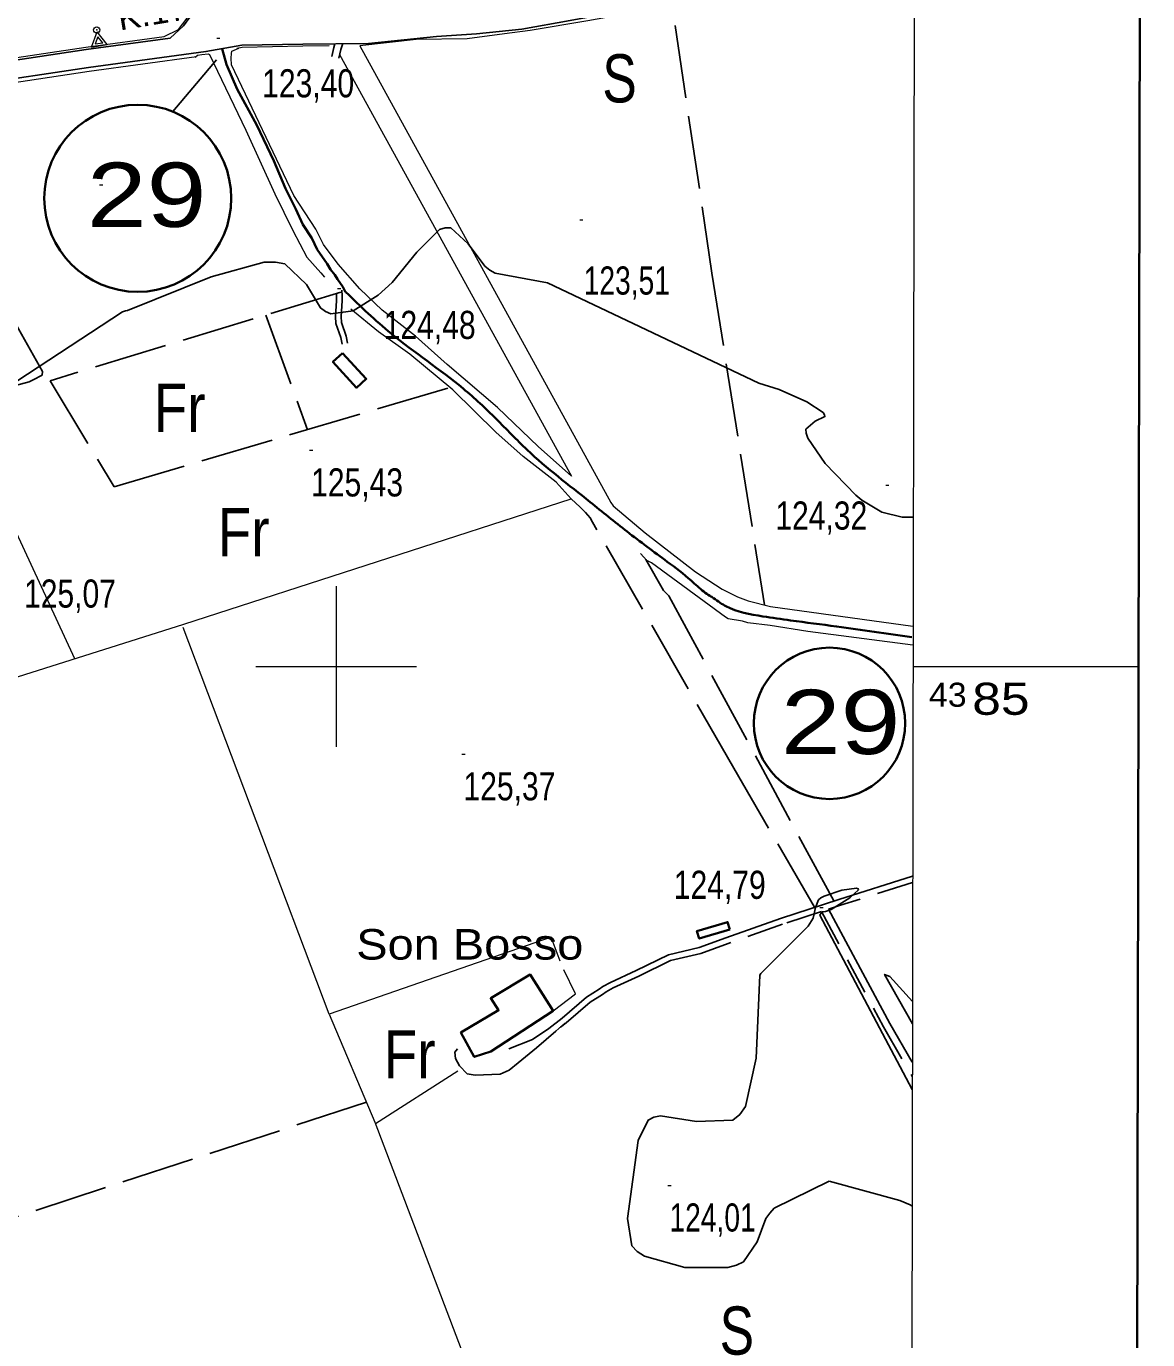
# Model space of a CAD drawing. Extents: x 483847 to 488453, y 4383581 to 4386795.
# Drawn here: x 487403.6 to 487752.5, y 4384790.5 to 4385199.2 of the extents above; entities that cross this region are included whole.
import ezdxf
from ezdxf.enums import TextEntityAlignment as Align

# ---------------------------------------------------------------- set-up
doc = ezdxf.new("R2010")
doc.units = 0
doc.header["$LTSCALE"] = 3.8
doc.header["$PDMODE"] = 32
doc.header["$PDSIZE"] = 1.9
for name, pattern in [('DOTTED', [1.5, 0.3, -1.2]), ('LONG_DASHED', [7.5, 6, -1.5]), ('MEDIUM_DASHED', [4.5, 3, -1.5])]:
    doc.linetypes.add(name, pattern=pattern)
for name, color, linetype, lineweight in [('1', 7, 'Continuous', 13), ('13', 7, 'Continuous', 25), ('2', 7, 'DOTTED', 13), ('25', 7, 'LONG_DASHED', 25), ('36', 7, 'Continuous', 25), ('38', 7, 'Continuous', 25), ('41', 7, 'Continuous', 13), ('47', 7, 'Continuous', 35), ('51', 7, 'Continuous', 13), ('6', 7, 'Continuous', 35), ('7', 7, 'Continuous', 13), ('8', 7, 'Continuous', 25)]:
    doc.layers.add(name, color=color, linetype=linetype, lineweight=lineweight)
doc.layers.add('31', color=7, linetype='Continuous')
doc.layers.add('5', color=7, linetype='Continuous')

msp = doc.modelspace()

# ---------------------------------------------------------------- linework, layer by layer
at = {"layer": '1'}
for p, q in [((487500, 4385025), (487500, 4384975)), ((487475, 4385000), (487525, 4385000)), ((487679.47, 4385000), (487749.65, 4385000))]:
    msp.add_line(p, q, dxfattribs=at)
at = {"layer": '1', "lineweight": 35}
msp.add_lwpolyline([(484035.03, 4386519.58), (487752.53, 4386512.52), (487747.86, 4384057.52), (484030.36, 4384064.59)], close=True, dxfattribs=at)
at = {"layer": '1'}
msp.add_lwpolyline([(484105.5, 4386448.1), (487681.9, 4386441.2), (487678, 4384129), (484100.5, 4384135.8)], close=True, dxfattribs=at)
at = {"layer": '25'}
for p, q in [((487478.05, 4385109.37), (487491.04, 4385073.7)), ((487509.45, 4384864.45), (487305.11, 4384797.64))]:
    msp.add_line(p, q, dxfattribs=at)
for points in [[(487605.49, 4385199.49), (487616.92, 4385122.4), (487633.25, 4385019.22)], [(487348.87, 4385070.84), (487382.28, 4385079.84), (487383.6, 4385083.12), (487404.46, 4385088.6), (487405.67, 4385089.19), (487408.47, 4385090.65), (487408.64, 4385091.85), (487380.97, 4385140.87), (487317.71, 4385128.68)], [(487501.43, 4385116.48), (487411, 4385088.96), (487430.86, 4385055.89), (487535.45, 4385086.85)], [(487648.8, 4384925.1), (487623.72, 4384968.41), (487579.8, 4385044.9), (487578.99, 4385046.26), (487577.59, 4385047.93), (487576.85, 4385048.69), (487575.89, 4385049.61), (487573.15, 4385052.2)], [(487654.85, 4384927.07), (487609.04, 4385011.84), (487603.48, 4385021.97), (487601.85, 4385023.72), (487596.36, 4385033.36)]]:
    msp.add_lwpolyline(points, dxfattribs=at)
at = {"layer": '36'}
for points in [[(486825.52, 4385103.44), (486853.12, 4385107.17), (486880.63, 4385110.38), (486915.74, 4385115.13), (486950.76, 4385119.43), (487008.87, 4385126.93), (487067.66, 4385134.49), (487152.91, 4385145.5), (487220.82, 4385155.63), (487295.65, 4385167.08), (487350.85, 4385175.59), (487422.95, 4385186.43), (487459.43, 4385191.37), (487470.68, 4385193.32), (487489.65, 4385193.71), (487510.01, 4385193.94), (487531.2, 4385196.06), (487543.67, 4385196.93), (487557.74, 4385198.3), (487572.8, 4385201.01), (487598.91, 4385205.81), (487622.06, 4385209.39), (487655.21, 4385214.16), (487679.8, 4385218.38)], [(487455.81, 4385215.58), (487456.62, 4385209.72), (487455.81, 4385205.68), (487454.49, 4385202.09), (487452.5, 4385199.34), (487448.32, 4385195.53)], [(486788.13, 4385103.8), (486799.99, 4385105.59), (486824.76, 4385108.99), (486852.42, 4385112.73), (486879.93, 4385115.94), (486915.02, 4385120.69), (486950.06, 4385124.99), (487008.15, 4385132.49), (487066.94, 4385140.05), (487152.14, 4385151.05), (487219.98, 4385161.17), (487294.79, 4385172.63), (487350, 4385181.14), (487422.16, 4385191.98), (487448.32, 4385195.53)]]:
    msp.add_lwpolyline(points, dxfattribs=at)
at = {"layer": '38'}
for p, q in [((487679.36, 4384934.79), (487679.34, 4384934.78)), ((487679.25, 4384876.89), (487679.26, 4384876.87))]:
    msp.add_line(p, q, dxfattribs=at)
at = {"layer": '38', "linetype": 'MEDIUM_DASHED'}
for p, q in [((487679.36, 4384932.79), (487679.34, 4384932.79)), ((487679.24, 4384872.41), (487679.25, 4384872.39))]:
    msp.add_line(p, q, dxfattribs=at)
at = {"layer": '38'}
for points in [[(487499.62, 4385193.82), (487499.24, 4385192.62), (487498.6, 4385189.82)], [(487501.78, 4385117.18), (487501.83, 4385115.43), (487501.81, 4385113.77), (487501.59, 4385108.9), (487501.63, 4385107.1), (487503.13, 4385102.84), (487503.56, 4385100.63)], [(487679.34, 4384934.78), (487656.36, 4384927.55), (487638.26, 4384921.66), (487621.28, 4384915.6), (487612.93, 4384912.58), (487603.42, 4384910.3), (487593.39, 4384905.4), (487585.38, 4384901.75), (487582.98, 4384900.41), (487581.84, 4384899.59), (487577.88, 4384897.09), (487570.34, 4384890.65), (487566.12, 4384887.35), (487561.03, 4384884.01), (487553.76, 4384881.06)], [(487653.2, 4384924.53), (487672.28, 4384888.95), (487679.25, 4384876.89)], [(487537.76, 4384881.02), (487536.91, 4384879.98), (487537.11, 4384878.03), (487538.36, 4384875.76), (487540.8, 4384873.32), (487543.27, 4384872.84), (487551, 4384873.18), (487553.87, 4384874.41), (487556.6, 4384876.7), (487562.3, 4384881.42), (487568.37, 4384886.51), (487571.11, 4384889.02)]]:
    msp.add_lwpolyline(points, dxfattribs=at)
at = {"layer": '38', "linetype": 'MEDIUM_DASHED'}
for points in [[(487502.02, 4385193.85), (487501.45, 4385192.02), (487500.83, 4385189.31)], [(487500.04, 4385116.24), (487500.06, 4385115.42), (487500.04, 4385113.82), (487499.82, 4385108.92), (487499.86, 4385106.78), (487501.42, 4385102.37), (487501.82, 4385100.29)], [(487679.34, 4384932.79), (487656.93, 4384925.75), (487653.2, 4384924.53)], [(487651.03, 4384923.83), (487638.87, 4384919.86), (487621.92, 4384913.81), (487613.48, 4384910.76), (487604.06, 4384908.5), (487594.2, 4384903.68), (487586.23, 4384900.06), (487584, 4384898.8), (487582.9, 4384898.01), (487579.01, 4384895.55), (487571.54, 4384889.18), (487569.75, 4384887.78)], [(487651.03, 4384923.83), (487670.32, 4384887.86), (487679.24, 4384872.41)]]:
    msp.add_lwpolyline(points, dxfattribs=at)
at = {"layer": '41'}
for p, q in [((487423.82, 4385192.79), (487425.57, 4385197.47)), ((487428.75, 4385193.61), (487425.57, 4385197.47)), ((487423.82, 4385192.79), (487428.75, 4385193.61))]:
    msp.add_line(p, q, dxfattribs=at)
msp.add_lwpolyline([(487425.82, 4385195.99), (487424.98, 4385193.74), (487427.34, 4385194.14)], close=True, dxfattribs=at)
msp.add_point((487425.46, 4385198.13), dxfattribs=at)
at = {"layer": '47'}
for points in [[(487501.99, 4385097.56), (487509.35, 4385089.54), (487506.34, 4385086.77), (487498.98, 4385094.79)], [(487622.48, 4384918.15), (487612.96, 4384915.35), (487612.27, 4384917.7), (487621.79, 4384920.5)], [(487567.49, 4384892.9), (487548.1, 4384880.2), (487542.97, 4384878.54), (487538.8, 4384886.11), (487550.53, 4384893.07), (487548.11, 4384896.78), (487560.37, 4384904.18)]]:
    msp.add_lwpolyline(points, close=True, dxfattribs=at)
at = {"layer": '51'}
for p, q in [((487382.94, 4385079.31), (487418.61, 4385002.51)), ((487679.47, 4385012.54), (487679.49, 4385012.54)), ((487679.48, 4385006.7), (487679.46, 4385006.7)), ((487512.24, 4384857.84), (487537.81, 4384874.19))]:
    msp.add_line(p, q, dxfattribs=at)
for points in [[(487446.47, 4385196.1), (487450.9, 4385198.24), (487453.66, 4385201.8), (487454.46, 4385205.17), (487454.82, 4385209.52), (487454.85, 4385211.69), (487454.89, 4385214.69), (487452.92, 4385218.7), (487436.12, 4385261.03), (487431.32, 4385261.25), (487430.48, 4385265.47), (487383.24, 4385257.36)], [(487602.05, 4385205.23), (487578.28, 4385200.99), (487560.38, 4385197.95), (487552.34, 4385196.94), (487540.76, 4385195.3), (487524.85, 4385195.16), (487507.33, 4385193.16)], [(486912.94, 4385121.23), (486914.92, 4385121.49), (486949.96, 4385125.79), (487008.05, 4385133.29), (487066.84, 4385140.85), (487152.03, 4385151.85), (487219.86, 4385161.97), (487294.67, 4385173.43), (487349.88, 4385181.94), (487422.04, 4385192.78), (487446.47, 4385196.1)], [(487500.99, 4385190.47), (487573.17, 4385059.25), (487562.8, 4385068.48), (487550.22, 4385080.66), (487534.5, 4385094.02), (487524.65, 4385102.86), (487514.26, 4385110.89), (487507.38, 4385117.59), (487500.58, 4385125.2), (487496.02, 4385131.34), (487493.69, 4385136.1), (487486.86, 4385146.55), (487467.41, 4385187.28), (487467.36, 4385189.3), (487467.38, 4385190.8), (487467.54, 4385191.55), (487469.72, 4385192.48)], [(487497.78, 4385193.15), (487489.66, 4385193.06), (487470.74, 4385192.65), (487469.04, 4385192.36)], [(487507.33, 4385193.16), (487585.44, 4385051.04), (487586.17, 4385050.06), (487596.18, 4385041.59), (487611.84, 4385029.51), (487620.09, 4385024.06), (487624.86, 4385021.74), (487628.22, 4385020.49), (487635.1, 4385018.74), (487679.47, 4385012.54)], [(487456.52, 4385189.7), (487423.14, 4385185.17), (487351.03, 4385174.33), (487299.38, 4385166.37)], [(487456.1, 4385189.64), (487456.79, 4385190.28), (487458.15, 4385190.48), (487460.18, 4385190.68), (487460.62, 4385190.45), (487471.92, 4385166.95), (487480.86, 4385147.16), (487486.55, 4385135.68), (487490.86, 4385127.44), (487495.22, 4385122.57), (487496.4, 4385121.2)], [(487159, 4385145.12), (487158.4, 4385145.03), (487171.14, 4385112.51), (487193.04, 4385054.26), (487206.65, 4385019.55), (487211.62, 4385004.62), (487220.59, 4384981.16), (487228.71, 4384961.46), (487240.34, 4384930.53), (487243.55, 4384923.65), (487294.8, 4384955.56), (487310.53, 4384963.51), (487319.67, 4384968.18), (487325.42, 4384971.48), (487388.54, 4384993.01), (487452.61, 4385013.25), (487573.15, 4385052.2), (487568.49, 4385057.37), (487558.18, 4385065.39), (487549.66, 4385072.94), (487536.34, 4385086.11), (487522.92, 4385097.19), (487513.11, 4385104.16), (487504.51, 4385111.18)], [(487679.46, 4385006.7), (487646.77, 4385010.92), (487635.01, 4385012.82), (487628.12, 4385013.59), (487626.48, 4385014.14), (487621.99, 4385014.88), (487621.09, 4385015.34), (487598.15, 4385032.25), (487596.66, 4385033.03), (487594.66, 4385035.15)], [(487569.66, 4384908.33), (487566.84, 4384915.8), (487497.77, 4384891.87), (487452.34, 4385012.15)], [(487567.48, 4384892.9), (487574.47, 4384898.2), (487570.82, 4384905.68)], [(487497.77, 4384891.87), (487512.07, 4384858.28), (487548.44, 4384762.46), (487577.78, 4384689.63), (487611.09, 4384610.29), (487611.68, 4384609.45), (487612.42, 4384608.77), (487613.08, 4384608.01), (487615.18, 4384607.9), (487616.85, 4384608.93), (487647.34, 4384631.9), (487648.99, 4384631.73), (487662.87, 4384620.88), (487671.21, 4384611.53), (487676.44, 4384604.32), (487678.8, 4384601.17)]]:
    msp.add_lwpolyline(points, dxfattribs=at)
at = {"layer": '6', "lineweight": 25}
msp.add_line((487449.19, 4385172.72), (487462.74, 4385188.79), dxfattribs=at)
at = {"layer": '6'}
msp.add_lwpolyline([(487464.55, 4385192.26), (487465.84, 4385187.36), (487469.17, 4385179.71), (487475.3, 4385168.52), (487480.55, 4385157.4), (487484.26, 4385148.79), (487487.46, 4385142.3), (487489.64, 4385137.56), (487492.4, 4385133.28), (487494.08, 4385129.74), (487497.14, 4385125.28), (487498.2, 4385123.52), (487499.61, 4385121.88), (487500.43, 4385120.59), (487502.07, 4385118.13), (487502.9, 4385116.48)], dxfattribs=at)
for centre, radius in [((487438.23, 4385145.72), 29.1), ((487653.5, 4384982.35), 23.55)]:
    msp.add_circle(centre, radius, dxfattribs=at)
msp.add_spline([(487503.02, 4385116.48), (487517.08, 4385103.65), (487539.5, 4385086.52), (487549.79, 4385077.07), (487559.41, 4385067.47), (487578.99, 4385051.21), (487590.49, 4385042.04), (487603.03, 4385032.63), (487610.45, 4385026.75), (487614.38, 4385023.32), (487616.24, 4385022.01), (487617.43, 4385021.32), (487619.51, 4385019.87), (487621.29, 4385018.79), (487632.76, 4385015.64), (487641.4, 4385014.37), (487655.73, 4385012.48), (487679.12, 4385009.11)], degree=3, dxfattribs=at)
at = {"layer": '7'}
for p, q in [((487462.82, 4385195.59), (487463.82, 4385195.59)), ((487426.38, 4385149.96), (487427.38, 4385149.96)), ((487575.77, 4385139.04), (487576.77, 4385139.04)), ((487500.42, 4385117.61), (487501.42, 4385117.61)), ((487491.68, 4385067.31), (487492.68, 4385067.31)), ((487671.01, 4385056.41), (487672.01, 4385056.41)), ((487539.09, 4384972.76), (487540.09, 4384972.76)), ((487650.51, 4384925.02), (487651.51, 4384925.02)), ((487603.2, 4384838.58), (487604.2, 4384838.58))]:
    msp.add_line(p, q, dxfattribs=at)
at = {"layer": '8'}
for points in [[(487390.87, 4385082.51), (487433.5, 4385110.39), (487434.4, 4385110.67), (487435.05, 4385110.79), (487461.06, 4385121.25), (487477.6, 4385125.82), (487481.06, 4385125.84), (487484.04, 4385125.31), (487490.76, 4385118.91), (487495.15, 4385111.59), (487496.67, 4385110.5), (487498.31, 4385109.81), (487505.31, 4385110.66), (487513.1, 4385115.59), (487517.39, 4385119.57), (487525.05, 4385128.99), (487532.15, 4385136), (487533.92, 4385136.57), (487535.62, 4385136.56), (487541.06, 4385131.56), (487546.29, 4385124.6), (487547.85, 4385123.34), (487549.47, 4385122.38), (487565.78, 4385119.41), (487631.5, 4385088.17), (487637.8, 4385086.27), (487646.43, 4385082.34), (487651.51, 4385079.08), (487651.99, 4385078.38), (487652.08, 4385077.78), (487649.06, 4385076.39), (487646.12, 4385073.88), (487646.24, 4385072.59), (487646.78, 4385071.03), (487652.14, 4385063.23), (487661.68, 4385053.37), (487663.57, 4385051.83), (487669.82, 4385048.05), (487676.1, 4385046.55), (487679.55, 4385046.51)], [(487653.38, 4384839.88), (487636.33, 4384831.45), (487634.92, 4384829.93), (487633.72, 4384828.27), (487631.03, 4384821.02), (487626.74, 4384814.79), (487624.52, 4384813.77), (487621.86, 4384813.05), (487608.53, 4384812.99), (487595.91, 4384816.5), (487593.69, 4384818.03), (487592.03, 4384819.8), (487590.64, 4384828.22), (487594, 4384852.49), (487597.03, 4384858.9), (487598.79, 4384859.75), (487600.96, 4384860.2), (487612.13, 4384858.49), (487623.37, 4384858.89), (487625.58, 4384860.66), (487627.39, 4384863.16), (487630.67, 4384878.21), (487631.86, 4384904.03), (487632.17, 4384904.5), (487646.83, 4384919.24), (487648.4, 4384921.67), (487649.15, 4384924.99), (487650.05, 4384927.42), (487650.82, 4384928.03), (487651.82, 4384928.6), (487657.3, 4384930.42), (487661.93, 4384931.04), (487662.39, 4384930.86), (487662.48, 4384930.53), (487659.85, 4384928.07), (487654, 4384924.39), (487652.24, 4384923.8), (487651.38, 4384923.69), (487651.18, 4384923.59), (487651.01, 4384923.45), (487650.53, 4384922.68), (487679.25, 4384868.38)], [(487679.29, 4384895.84), (487672.28, 4384903.6), (487670.64, 4384904.23), (487679.28, 4384888.82)], [(487679.19, 4384832.06), (487678.57, 4384832.54), (487675.44, 4384833.84), (487653.38, 4384839.88)]]:
    msp.add_lwpolyline(points, dxfattribs=at)

# ---------------------------------------------------------------- texts
at = {"layer": '13', "width": 1.25}
for p in [(487441.01, 4385136.82), (487656.96, 4384972.79)]:
    msp.add_text('29', height=20, dxfattribs=at).set_placement(p, align=Align.CENTER)
at = {"layer": '2'}
for s, height, width, p in [('43', 7.5, 1.05, (487684.46, 4384987.5)), ('85  ', 10, 1.2, (487697.91, 4384985))]:
    msp.add_text(s, height=height, dxfattribs=dict(at, width=width)).set_placement(p)
at = {"layer": '31'}
for s, width, p in [('S', 0.8, (487588.17, 4385175.55)), ('Fr', 0.85, (487451.3, 4385073.03)), ('Fr', 0.85, (487471.21, 4385034.35)), ('Fr', 0.85, (487522.87, 4384871.85)), ('S', 0.8, (487624.67, 4384785.9))]:
    msp.add_text(s, height=15, dxfattribs=dict(at, width=width)).set_placement(p, align=Align.CENTER)
at = {"layer": '41', "width": 1.05}
msp.add_text('K.17', height=7.5, rotation=9.473, dxfattribs=at).set_placement((487432.7, 4385197.92))
at = {"layer": '5', "width": 1.15}
msp.add_text('Son Bosso', height=9.5, dxfattribs=at).set_placement((487506.24, 4384908.83))
at = {"layer": '7'}
for s, width, p in [('123,40', 0.8, (487476.95, 4385177.13)), ('123,51', 0.75, (487577.01, 4385115.76)), ('124,48', 0.8, (487514.76, 4385101.95)), ('125,43', 0.8, (487492.18, 4385052.94)), ('124,32', 0.8, (487636.63, 4385042.63)), ('125,07', 0.8, (487402.84, 4385018.35)), ('125,37', 0.8, (487539.59, 4384958.39)), ('124,79', 0.8, (487605.03, 4384927.73)), ('124,01', 0.75, (487603.7, 4384824.21))]:
    msp.add_text(s, height=8.75, dxfattribs=dict(at, width=width)).set_placement(p)

doc.saveas('drawing.dxf')
